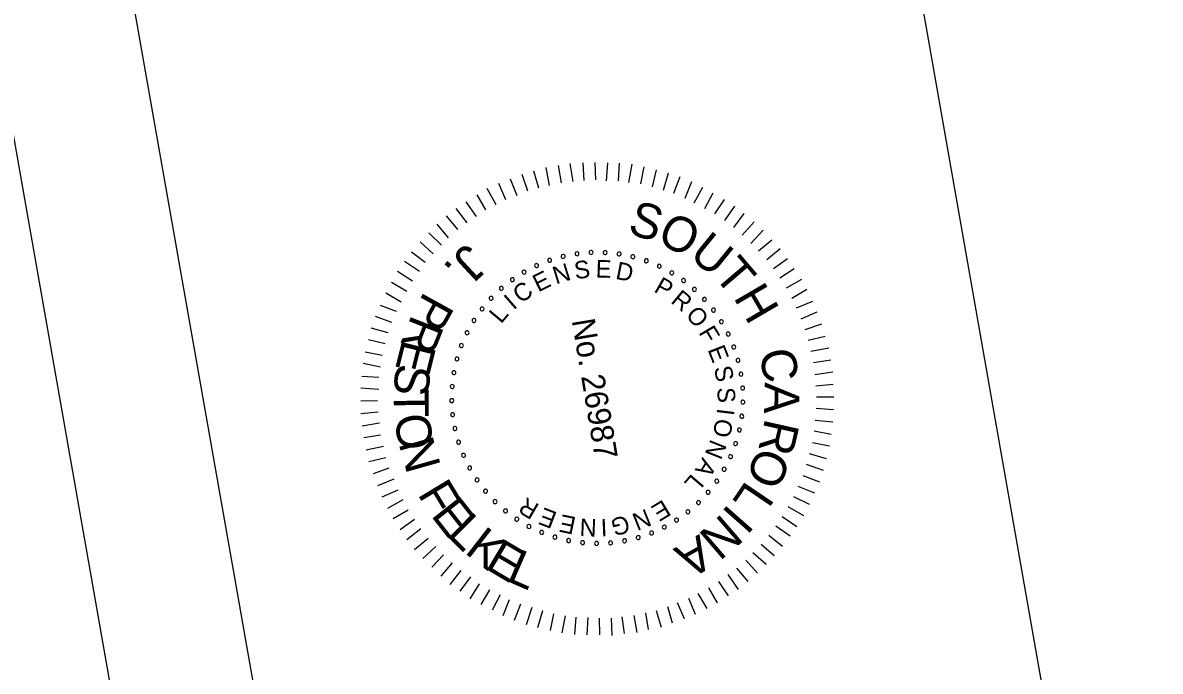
# Model space of a CAD drawing. Extents: x 1971280 to 1971503, y 796034 to 796348.
# Drawn here: x 1971311.8 to 1971344.03, y 796120.9 to 796139.28 of the extents above; entities that cross this region are included whole.
import ezdxf

# ---------------------------------------------------------------- set-up
doc = ezdxf.new("R2010")
doc.units = 0
for name, color, linetype in [('BR_BORDER LINES', 7, 'Continuous'), ('BR_TEXT', 7, 'Continuous'), ('Level 31', 7, 'Continuous')]:
    doc.layers.add(name, color=color, linetype=linetype)

msp = doc.modelspace()

# ---------------------------------------------------------------- linework, layer by layer
at = {"layer": 'BR_BORDER LINES'}
for p, q in [((1971286.058, 796303.806), (1971332.766, 796038.559)), ((1971336.584, 796143.739), (1971344.027, 796101.468))]:
    msp.add_line(p, q, dxfattribs=at)
at = {"layer": 'BR_TEXT'}
for p, q in [((1971326.728, 796134.669), (1971326.629, 796135.175)), ((1971327.064, 796134.74), (1971326.982, 796135.234)), ((1971327.392, 796134.781), (1971327.306, 796135.288)), ((1971327.706, 796134.812), (1971327.679, 796135.309)), ((1971328.037, 796134.833), (1971328.017, 796135.324)), ((1971328.335, 796134.799), (1971328.374, 796135.314)), ((1971328.676, 796134.801), (1971328.71, 796135.301)), ((1971328.976, 796134.754), (1971329.07, 796135.271)), ((1971329.31, 796134.712), (1971329.402, 796135.201)), ((1971329.638, 796134.628), (1971329.758, 796135.114)), ((1971325.81, 796134.376), (1971325.619, 796134.852)), ((1971326.108, 796134.51), (1971325.952, 796134.978)), ((1971326.427, 796134.598), (1971326.284, 796135.075)), ((1971329.952, 796134.541), (1971330.093, 796135.024)), ((1971330.245, 796134.451), (1971330.424, 796134.92)), ((1971325.212, 796134.123), (1971324.961, 796134.582)), ((1971325.487, 796134.266), (1971325.291, 796134.728)), ((1971330.568, 796134.31), (1971330.754, 796134.78)), ((1971330.827, 796134.18), (1971331.072, 796134.625)), ((1971324.654, 796133.793), (1971324.362, 796134.21)), ((1971324.923, 796133.977), (1971324.676, 796134.409)), ((1971331.125, 796134.021), (1971331.364, 796134.465)), ((1971331.408, 796133.866), (1971331.682, 796134.268)), ((1971324.393, 796133.61), (1971324.081, 796134.017)), ((1971331.691, 796133.677), (1971331.977, 796134.087)), ((1971331.946, 796133.483), (1971332.242, 796133.874)), ((1971323.865, 796133.187), (1971323.543, 796133.572)), ((1971324.124, 796133.426), (1971323.802, 796133.81)), ((1971332.185, 796133.259), (1971332.525, 796133.643)), ((1971323.663, 796132.979), (1971323.306, 796133.323)), ((1971332.433, 796133.029), (1971332.78, 796133.407)), ((1971323.433, 796132.732), (1971323.056, 796133.072)), ((1971332.643, 796132.813), (1971333.028, 796133.129)), ((1971332.879, 796132.568), (1971333.264, 796132.883)), ((1971323.202, 796132.491), (1971322.819, 796132.782)), ((1971333.066, 796132.321), (1971333.471, 796132.604)), ((1971322.839, 796131.957), (1971322.418, 796132.228)), ((1971323.037, 796132.227), (1971322.619, 796132.519)), ((1971333.25, 796132.052), (1971333.659, 796132.316)), ((1971322.679, 796131.666), (1971322.253, 796131.921)), ((1971333.437, 796131.77), (1971333.869, 796132.016)), ((1971322.52, 796131.367), (1971322.089, 796131.615)), ((1971333.591, 796131.476), (1971334.015, 796131.728)), ((1971322.391, 796131.095), (1971321.938, 796131.27)), ((1971333.72, 796131.205), (1971334.182, 796131.394)), ((1971322.262, 796130.788), (1971321.795, 796130.96)), ((1971333.855, 796130.893), (1971334.303, 796131.087)), ((1971322.152, 796130.491), (1971321.676, 796130.628)), ((1971333.969, 796130.592), (1971334.437, 796130.747)), ((1971322.065, 796130.177), (1971321.593, 796130.293)), ((1971334.055, 796130.287), (1971334.53, 796130.401)), ((1971334.127, 796129.978), (1971334.635, 796130.064)), ((1971321.981, 796129.85), (1971321.506, 796129.944)), ((1971334.203, 796129.65), (1971334.691, 796129.732)), ((1971321.938, 796129.523), (1971321.448, 796129.622)), ((1971334.238, 796129.315), (1971334.748, 796129.386)), ((1971321.891, 796129.223), (1971321.406, 796129.253)), ((1971334.271, 796128.994), (1971334.758, 796129.04)), ((1971321.892, 796128.888), (1971321.384, 796128.922)), ((1971334.289, 796128.683), (1971334.783, 796128.682)), ((1971321.855, 796128.562), (1971321.383, 796128.56)), ((1971334.281, 796128.354), (1971334.766, 796128.325)), ((1971321.874, 796128.245), (1971321.381, 796128.197)), ((1971321.906, 796127.93), (1971321.418, 796127.849)), ((1971334.222, 796127.711), (1971334.704, 796127.618)), ((1971334.254, 796128.016), (1971334.755, 796127.974)), ((1971321.941, 796127.595), (1971321.46, 796127.515)), ((1971334.172, 796127.383), (1971334.661, 796127.29)), ((1971322.017, 796127.267), (1971321.532, 796127.171)), ((1971334.084, 796127.076), (1971334.561, 796126.933)), ((1971322.091, 796126.952), (1971321.609, 796126.836)), ((1971333.997, 796126.768), (1971334.478, 796126.599)), ((1971322.175, 796126.653), (1971321.729, 796126.494)), ((1971333.904, 796126.447), (1971334.373, 796126.268)), ((1971322.317, 796126.349), (1971321.847, 796126.159)), ((1971333.759, 796126.151), (1971334.23, 796125.958)), ((1971322.425, 796126.034), (1971321.979, 796125.833)), ((1971333.634, 796125.858), (1971334.081, 796125.641)), ((1971322.569, 796125.758), (1971322.137, 796125.512)), ((1971322.716, 796125.463), (1971322.298, 796125.218)), ((1971333.474, 796125.567), (1971333.92, 796125.315)), ((1971322.899, 796125.201), (1971322.495, 796124.911)), ((1971333.32, 796125.284), (1971333.728, 796125.004)), ((1971323.082, 796124.939), (1971322.683, 796124.622)), ((1971333.141, 796125.024), (1971333.543, 796124.743)), ((1971323.288, 796124.667), (1971322.903, 796124.345)), ((1971332.72, 796124.501), (1971333.086, 796124.187)), ((1971332.934, 796124.76), (1971333.328, 796124.443)), ((1971323.508, 796124.433), (1971323.14, 796124.1)), ((1971323.722, 796124.197), (1971323.39, 796123.849)), ((1971332.488, 796124.267), (1971332.864, 796123.933)), ((1971323.968, 796123.974), (1971323.649, 796123.594)), ((1971332.287, 796124.053), (1971332.614, 796123.683)), ((1971324.213, 796123.758), (1971323.904, 796123.358)), ((1971324.487, 796123.574), (1971324.185, 796123.175)), ((1971331.778, 796123.64), (1971332.071, 796123.223)), ((1971332.025, 796123.828), (1971332.346, 796123.45)), ((1971324.728, 796123.384), (1971324.465, 796122.958)), ((1971325.028, 796123.212), (1971324.778, 796122.794)), ((1971331.229, 796123.263), (1971331.473, 796122.844)), ((1971331.511, 796123.449), (1971331.782, 796123.035)), ((1971325.324, 796123.067), (1971325.098, 796122.632)), ((1971325.584, 796122.929), (1971325.403, 796122.474)), ((1971330.658, 796122.972), (1971330.853, 796122.518)), ((1971330.929, 796123.101), (1971331.181, 796122.677)), ((1971325.905, 796122.802), (1971325.724, 796122.34)), ((1971326.22, 796122.709), (1971326.059, 796122.215)), ((1971326.528, 796122.614), (1971326.386, 796122.131)), ((1971329.44, 796122.559), (1971329.519, 796122.085)), ((1971329.749, 796122.625), (1971329.884, 796122.153)), ((1971330.065, 796122.733), (1971330.204, 796122.277)), ((1971330.338, 796122.849), (1971330.539, 796122.395)), ((1971326.842, 796122.527), (1971326.747, 796122.052)), ((1971327.165, 796122.47), (1971327.071, 796121.988)), ((1971327.469, 796122.438), (1971327.433, 796121.945)), ((1971327.812, 796122.426), (1971327.784, 796121.933)), ((1971328.135, 796122.41), (1971328.139, 796121.93)), ((1971328.469, 796122.41), (1971328.489, 796121.919)), ((1971328.776, 796122.448), (1971328.842, 796121.972)), ((1971329.118, 796122.484), (1971329.199, 796122.004))]:
    msp.add_line(p, q, dxfattribs=at)
for centre, start, end in [((1971326.729, 796132.548), 19.2061, 199.2061), ((1971326.729, 796132.548), 199.2061, 19.2061), ((1971327.112, 796132.66), 13.6677, 193.6677), ((1971327.112, 796132.66), 193.6677, 13.6677), ((1971327.504, 796132.735), 8.1292, 188.1292), ((1971327.504, 796132.735), 188.1292, 8.1292), ((1971327.901, 796132.771), 2.5907, 182.5907), ((1971327.901, 796132.771), 182.5907, 2.5907), ((1971328.299, 796132.769), 357.0523, 177.0523), ((1971328.299, 796132.769), 177.0523, 357.0523), ((1971328.696, 796132.729), 351.5138, 171.5138), ((1971328.696, 796132.729), 171.5138, 351.5138), ((1971329.087, 796132.65), 165.9753, 345.9753), ((1971329.087, 796132.65), 345.9753, 165.9753), ((1971329.468, 796132.534), 160.4369, 340.4369), ((1971329.468, 796132.534), 340.4369, 160.4369), ((1971326.005, 796132.216), 30.283, 210.283), ((1971326.005, 796132.216), 210.283, 30.283), ((1971326.359, 796132.4), 24.7446, 204.7446), ((1971326.359, 796132.4), 204.7446, 24.7446), ((1971329.836, 796132.382), 154.8984, 334.8984), ((1971329.836, 796132.382), 334.8984, 154.8984), ((1971330.188, 796132.195), 149.36, 329.36), ((1971330.188, 796132.195), 329.36, 149.36), ((1971325.671, 796132), 35.8215, 215.8215), ((1971325.671, 796132), 215.8215, 35.8215), ((1971330.521, 796131.975), 143.8215, 323.8215), ((1971330.521, 796131.975), 323.8215, 143.8215), ((1971325.359, 796131.751), 41.36, 221.36), ((1971325.359, 796131.751), 221.36, 41.36), ((1971330.83, 796131.724), 138.283, 318.283), ((1971330.83, 796131.724), 318.283, 138.283), ((1971325.072, 796131.474), 46.8984, 226.8984), ((1971325.072, 796131.474), 226.8984, 46.8984), ((1971331.114, 796131.444), 132.7446, 312.7446), ((1971331.114, 796131.444), 312.7446, 132.7446), ((1971324.814, 796131.171), 52.4369, 232.4369), ((1971324.814, 796131.171), 232.4369, 52.4369), ((1971331.37, 796131.138), 127.2061, 307.2061), ((1971331.37, 796131.138), 307.2061, 127.2061), ((1971324.585, 796130.844), 57.9753, 237.9753), ((1971324.585, 796130.844), 237.9753, 57.9753), ((1971331.594, 796130.808), 121.6677, 301.6677), ((1971331.594, 796130.808), 301.6677, 121.6677), ((1971324.39, 796130.497), 63.5138, 243.5138), ((1971324.39, 796130.497), 243.5138, 63.5138), ((1971331.786, 796130.459), 116.1292, 296.1292), ((1971331.786, 796130.459), 296.1292, 116.1292), ((1971324.229, 796130.132), 69.0523, 249.0523), ((1971324.229, 796130.132), 249.0523, 69.0523), ((1971331.944, 796130.093), 110.5907, 290.5907), ((1971331.944, 796130.093), 290.5907, 110.5907), ((1971324.104, 796129.754), 74.5907, 254.5907), ((1971324.104, 796129.754), 254.5907, 74.5907), ((1971332.065, 796129.713), 105.0523, 285.0523), ((1971332.065, 796129.713), 285.0523, 105.0523), ((1971324.016, 796129.365), 80.1292, 260.1292), ((1971324.016, 796129.365), 260.1292, 80.1292), ((1971332.149, 796129.323), 99.5138, 279.5138), ((1971332.149, 796129.323), 279.5138, 99.5138), ((1971323.966, 796128.969), 85.6677, 265.6677), ((1971323.966, 796128.969), 265.6677, 85.6677), ((1971332.195, 796128.927), 93.9753, 273.9753), ((1971332.195, 796128.927), 273.9753, 93.9753), ((1971323.954, 796128.571), 91.2061, 271.2061), ((1971323.954, 796128.571), 271.2061, 91.2061), ((1971332.203, 796128.529), 88.4369, 268.4369), ((1971332.203, 796128.529), 268.4369, 88.4369), ((1971323.981, 796128.173), 96.7446, 276.7446), ((1971323.981, 796128.173), 276.7446, 96.7446), ((1971332.172, 796128.131), 82.8984, 262.8984), ((1971332.172, 796128.131), 262.8984, 82.8984), ((1971324.046, 796127.78), 102.283, 282.283), ((1971324.046, 796127.78), 282.283, 102.283), ((1971332.103, 796127.739), 77.36, 257.36), ((1971332.103, 796127.739), 257.36, 77.36), ((1971324.149, 796127.395), 107.8215, 287.8215), ((1971324.149, 796127.395), 287.8215, 107.8215), ((1971331.996, 796127.355), 71.8215, 251.8215), ((1971331.996, 796127.355), 251.8215, 71.8215), ((1971324.288, 796127.021), 113.36, 293.36), ((1971324.288, 796127.021), 293.36, 113.36), ((1971331.853, 796126.983), 66.283, 246.283), ((1971331.853, 796126.983), 246.283, 66.283), ((1971324.463, 796126.663), 118.8984, 298.8984), ((1971324.463, 796126.663), 298.8984, 118.8984), ((1971331.674, 796126.626), 60.7446, 240.7446), ((1971331.674, 796126.626), 240.7446, 60.7446), ((1971324.672, 796126.323), 124.4369, 304.4369), ((1971324.672, 796126.323), 304.4369, 124.4369), ((1971331.462, 796126.289), 55.2061, 235.2061), ((1971331.462, 796126.289), 235.2061, 55.2061), ((1971324.912, 796126.005), 129.9753, 309.9753), ((1971324.912, 796126.005), 309.9753, 129.9753), ((1971325.182, 796125.712), 315.5138, 135.5138), ((1971331.219, 796125.973), 49.6677, 229.6677), ((1971331.219, 796125.973), 229.6677, 49.6677), ((1971325.182, 796125.712), 135.5138, 315.5138), ((1971325.479, 796125.446), 141.0523, 321.0523), ((1971325.479, 796125.446), 321.0523, 141.0523), ((1971330.646, 796125.42), 38.5907, 218.5907), ((1971330.646, 796125.42), 218.5907, 38.5907), ((1971330.946, 796125.683), 44.1292, 224.1292), ((1971330.946, 796125.683), 224.1292, 44.1292), ((1971325.8, 796125.21), 146.5907, 326.5907), ((1971325.8, 796125.21), 326.5907, 146.5907), ((1971330.322, 796125.187), 33.0523, 213.0523), ((1971330.322, 796125.187), 213.0523, 33.0523), ((1971326.143, 796125.006), 152.1292, 332.1292), ((1971326.143, 796125.006), 332.1292, 152.1292), ((1971326.504, 796124.836), 157.6677, 337.6677), ((1971326.504, 796124.836), 337.6677, 157.6677), ((1971329.615, 796124.821), 21.9753, 201.9753), ((1971329.615, 796124.821), 201.9753, 21.9753), ((1971329.977, 796124.987), 27.5138, 207.5138), ((1971329.977, 796124.987), 207.5138, 27.5138), ((1971326.879, 796124.702), 163.2061, 343.2061), ((1971326.879, 796124.702), 343.2061, 163.2061), ((1971327.266, 796124.605), 168.7446, 348.7446), ((1971327.266, 796124.605), 348.7446, 168.7446), ((1971327.66, 796124.545), 354.283, 174.283), ((1971327.66, 796124.545), 174.283, 354.283), ((1971328.058, 796124.524), 359.8215, 179.8215), ((1971328.058, 796124.524), 179.8215, 359.8215), ((1971328.456, 796124.541), 5.36, 185.36), ((1971328.456, 796124.541), 185.36, 5.36), ((1971328.851, 796124.597), 10.8984, 190.8984), ((1971328.851, 796124.597), 190.8984, 10.8984), ((1971329.238, 796124.69), 16.4369, 196.4369), ((1971329.238, 796124.69), 196.4369, 16.4369)]:
    msp.add_arc(centre, 0.0561, start, end, dxfattribs=at)
at = {"layer": 'Level 31'}
msp.add_line((1971279.575, 796317.557), (1971329.522, 796033.921), dxfattribs=at)

# ---------------------------------------------------------------- texts
at = {"layer": 'BR_TEXT'}
for s, height, rotation, p in [('S', 0.991, 343.2381, (1971328.907, 796133.317)), ('O', 0.993, 332.0137, (1971329.723, 796133.092)), ('U', 0.993, 320.7892, (1971330.646, 796132.649)), ('J', 0.988, 222.9429, (1971324.386, 796133.062)), ('S', 0.498, 7.773, (1971327.459, 796132.01)), ('E', 0.498, 358.2258, (1971328.027, 796132.064)), ('T', 0.993, 310.4862, (1971331.347, 796132.113)), ('.', 0.988, 229.3843, (1971323.911, 796132.621)), ('E', 0.498, 26.5225, (1971326.408, 796131.637)), ('N', 0.498, 17.3201, (1971326.908, 796131.863)), ('D', 0.498, 349.0234, (1971328.575, 796132.026)), ('C', 0.498, 36.4136, (1971325.917, 796131.308)), ('P', 0.498, 329.9291, (1971329.655, 796131.672)), ('H', 0.993, 300.3507, (1971331.922, 796131.5)), ('P', 0.988, 241.0904, (1971323.187, 796131.693)), ('I', 0.498, 41.088, (1971325.707, 796131.124)), ('R', 0.498, 320.3819, (1971330.136, 796131.366)), ('R', 0.988, 248.5229, (1971322.832, 796131.036)), ('L', 0.498, 49.9465, (1971325.352, 796130.731)), ('O', 0.498, 310.8347, (1971330.56, 796130.985)), ('No. 26987', 0.654, 279.5138, (1971327.352, 796130.846)), ('F', 0.498, 300.5997, (1971330.937, 796130.504)), ('E', 0.988, 255.9554, (1971322.564, 796130.338)), ('E', 0.498, 291.3973, (1971331.198, 796130.021)), ('C', 0.993, 279.5352, (1971332.665, 796129.97)), ('S', 0.988, 263.0162, (1971322.395, 796129.648)), ('S', 0.498, 282.195, (1971331.379, 796129.502)), ('A', 0.993, 268.1851, (1971332.826, 796129.094)), ('T', 0.988, 270.4487, (1971322.311, 796128.905)), ('S', 0.498, 272.6478, (1971331.476, 796128.94)), ('O', 0.988, 278.1289, (1971322.325, 796128.132)), ('O', 0.498, 258.4262, (1971331.446, 796128.092)), ('I', 0.498, 263.1006, (1971331.479, 796128.37)), ('R', 0.993, 257.4214, (1971332.841, 796128.095)), ('N', 0.988, 285.8091, (1971322.443, 796127.368)), ('N', 0.498, 248.1911, (1971331.295, 796127.5)), ('O', 0.991, 246.5739, (1971332.679, 796127.317)), ('A', 0.498, 238.6439, (1971331.061, 796126.98)), ('L', 0.498, 229.4416, (1971330.757, 796126.522)), ('F', 0.988, 301.1075, (1971322.974, 796125.928)), ('L', 0.993, 235.9358, (1971332.301, 796126.337)), ('E', 0.988, 308.1684, (1971323.344, 796125.321)), ('R', 0.498, 149.769, (1971326.465, 796125.61)), ('E', 0.498, 158.9713, (1971326.97, 796125.393)), ('N', 0.498, 201.8336, (1971329.47, 796125.515)), ('E', 0.498, 211.036, (1971329.951, 796125.78)), ('I', 0.993, 228.6483, (1971331.815, 796125.671)), ('L', 0.988, 315.2292, (1971323.786, 796124.765)), ('E', 0.498, 168.1737, (1971327.503, 796125.26)), ('N', 0.498, 177.7209, (1971328.071, 796125.213)), ('I', 0.498, 182.3953, (1971328.35, 796125.225)), ('G', 0.498, 192.2864, (1971328.932, 796125.325)), ('N', 0.993, 220.6906, (1971331.626, 796125.389)), ('K', 0.988, 322.29, (1971324.293, 796124.268)), ('E', 0.988, 329.3509, (1971324.858, 796123.836)), ('A', 0.993, 209.4662, (1971330.975, 796124.794)), ('L', 0.988, 336.4117, (1971325.471, 796123.478))]:
    msp.add_text(s, height=height, rotation=rotation, dxfattribs=at).set_placement(p)

doc.saveas('drawing.dxf')
